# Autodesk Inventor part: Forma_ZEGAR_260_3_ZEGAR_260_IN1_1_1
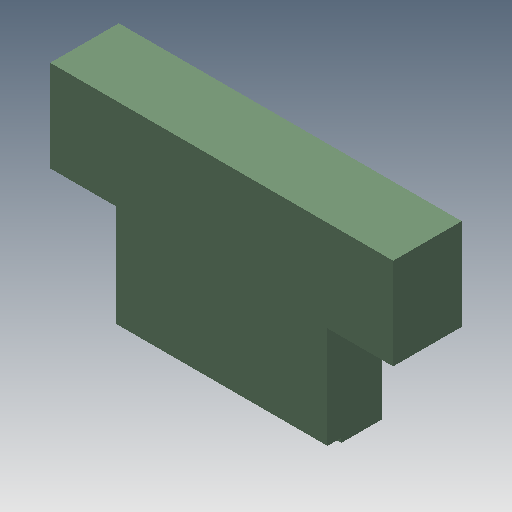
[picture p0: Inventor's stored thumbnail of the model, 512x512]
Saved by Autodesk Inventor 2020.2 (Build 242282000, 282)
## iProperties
Created: 2015-01
Part Number: Forma_ZEGAR_260_3_ZEGAR_260_IN1_1_1
Material: Ogólny
Document SubType Name: Modeling
Designer: F.Stasiak
Density: 1 g/cm^3
Appearance: Domyślna
Catalog Web Link: www.expertbooks.pl
Manager: www.cadconsulting.pl
Company: Fabian Stasiak CAD Consulting
Author: F.Stasiak
Subject: Zbiór ćwiczeń. Autodesk Inventor 2020. Kurs Professional
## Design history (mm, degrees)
node "Forma_ZEGAR_260_3_ZEGAR_260_IN1_Base"
feature "Bryła1::Forma_ZEGAR_260_3_ZEGAR_260_IN1_Base"
tag "Bryła wyprowadzona1"
node "Bryła1"
feature "Forma_ZEGAR_260_3_ZEGAR_260_IN1_Base_Bodies"
